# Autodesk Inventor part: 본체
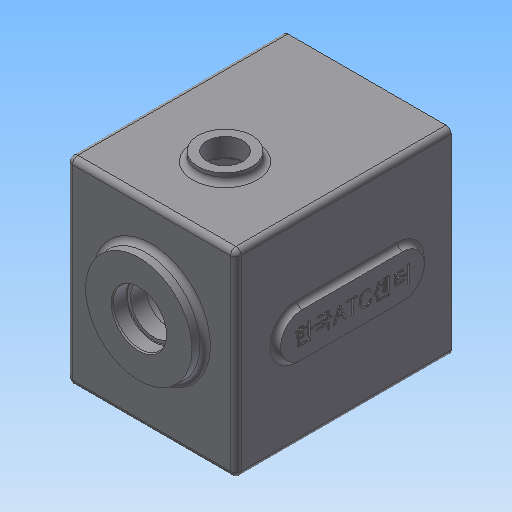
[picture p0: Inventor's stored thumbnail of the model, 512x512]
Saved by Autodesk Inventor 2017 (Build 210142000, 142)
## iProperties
Created: 2016-02
Part Number: 본체
Material: 알루미늄 6061
Document SubType Name: Modeling
Designer: mduedu
Density: 2.7 g/cm^3
Appearance: 기본값
Mass: 1511.55 g
Surface Area: 1073.15 cm^2
Volume: 559.832 cm^3
Author: mduedu
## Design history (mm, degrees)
sketch "스케치1"
  geometry: L1 (-47, -47)-(47, -47); L2 (47, -47)-(47, 63); L3 (47, 63)-(-47, 63); L4 (-47, 63)-(-47, -47); 2 further points
  constraints: 8 end point, 2 parallel, 1 horizontal, 1 midpoint, 1 perpendicular, 1 vertical alignment
  dimensions: "d0" = 94 distance of L2.end L3.end; "d155" = 110 distance of L1.end L2.end; "d156" = 47 distance from line of L1 point (0, 0)
extrude "돌출1" new body sketch "스케치1" distance "d2" = 120; taper "d3" = 0 deg
sketch "스케치3"
  geometry: L1 (47, -47)-(-47, -47) reference; L2 (47, 63)-(47, -47) reference; L3 (-47, 63)-(47, 63) reference; L4 (-47, -47)-(-47, 63) reference; L5 (37, 53)-(37, -37); L6 (37, -37)-(-37, -37); L7 (-37, -37)-(-37, 53); L8 (-37, 53)-(37, 53); 1 further point
  constraints: 8 end point, 3 other
  dimensions: "d226" = 10 distance between parallel lines of L8 L3
extrude "돌출3" cut sketch "스케치3" distance "d11" = 110; taper "d12" = 0 deg
sketch "스케치4"
  geometry: C1 r 21 at (0, 11); 1 further point
  constraints: 1 centre point, 1 vertical alignment
  dimensions: "d13" = 21 radius of C1; "d227" = 11 distance of point (0, 0) C1.centre
extrude "돌출4" join sketch "스케치4" distance "d16" = 7; taper "d17" = 0 deg
sketch "스케치5"
  geometry: C1 r 15 at (0, -20); 1 further point
  constraints: 1 centre point, 1 vertical alignment
  dimensions: "d18" = 15 radius of C1; "d20" = 20 distance of point (0, 0) C1.centre
extrude "돌출5" join sketch "스케치5" distance "d21" = 7; taper "d22" = 0 deg
sketch "스케치6"
  geometry: C1 r 30 at (0, 11); A1 r 21 centre (0, 11) between (8.978, -7.984) and (-8.978, -7.984) reference; 1 further point
  constraints: 1 centre point, 1 coincident
  dimensions: "d228" = 60 diameter of C1
extrude "돌출6" join sketch "스케치6" distance "d25" = 7; taper "d26" = -3 deg
hole "구멍1" diameter "d29" = 30; stored, may be unused: countersink angle "d33" = 90 deg, drill point angle "d35" = 0 deg; dims "d30" = 6, "d31" = 4, "d32" = 2, "d34" = 7, "d269" = 10, "d270" = 10
hole "구멍2" diameter "d38" = 22; stored, may be unused: countersink angle "d42" = 90 deg, drill point angle "d44" = 0 deg; dims "d36" = 10, "d37" = 10, "d39" = 6, "d40" = 4, "d41" = 2, "d43" = 7
hole "구멍3" diameter "d47" = 19; stored, may be unused: countersink angle "d51" = 90 deg, drill point angle "d53" = 0 deg; dims "d45" = 10, "d46" = 10, "d48" = 6, "d49" = 4, "d50" = 2, "d52" = 1
hole "구멍4" diameter "d56" = 30; stored, may be unused: countersink angle "d60" = 90 deg, drill point angle "d62" = 0 deg; dims "d57" = 6, "d58" = 4, "d59" = 2, "d61" = 8.3, "d271" = 10, "d272" = 10
hole "구멍5" diameter "d65" = 26; stored, may be unused: countersink angle "d69" = 90 deg, drill point angle "d71" = 0 deg; dims "d66" = 6, "d67" = 4, "d68" = 2, "d70" = 8, "d267" = 10, "d268" = 10
fillet "모깎기2" dims "d73" = 0.3
fillet "모깎기3" dims "d74" = 2
chamfer "모따기1" distance "d75" = 1; stored, may be unused: second distance "d76" = 2, angle "d77" = 45 deg
fillet "모깎기4" dims "d78" = 3
fillet "모깎기23" dims "d240" = 1
fillet "모깎기20" dims "d229" = 3
sketch "스케치23"
  geometry: L1 (-37, 53)-(37, 53) reference; L2 (37, 53)-(37, -37) reference; L3 (37, -37)-(-37, -37) reference; L4 (-37, -37)-(-37, 53) reference; L5 (44, -47)-(-44, -47) reference; L6 (47, 60)-(47, -44) reference; L7 (-44, 63)-(44, 63) reference; L8 (-47, -44)-(-47, 60) reference; C1 r 10 at (-37, 53); C2 r 10 at (37, 53); C3 r 10 at (-37, -37); C4 r 10 at (37, -37); A1 r 3 centre (-44, -44) between (-47, -44) and (-44, -47) reference; A2 r 3 centre (44, -44) between (44, -47) and (47, -44) reference; A3 r 3 centre (44, 60) between (47, 60) and (44, 63) reference; A4 r 3 centre (-44, 60) between (-44, 63) and (-47, 60) reference; 1 further point
  constraints: 4 centre point, 4 coincident, 3 equal radius
  dimensions: "d230" = 20 diameter of C1
extrude "돌출22" join sketch "스케치23" stored distance "d235" = 10; taper "d236" = 0 deg
fillet "모깎기21" dims "d237" = 3
node "작업 평면1"
fillet "모깎기22" dims "d239" = 1
sketch "스케치12"
  geometry: A1 r 10 centre (-37, 53) between (-34.692, 43.27) and (-27.27, 50.692) reference; A2 r 10 centre (37, 53) between (27.27, 50.692) and (34.692, 43.27) reference; A3 r 10 centre (37, -37) between (34.692, -27.27) and (27.27, -34.692) reference; A4 r 10 centre (-37, -37) between (-27.27, -34.692) and (-34.692, -27.27) reference; 5 further points
  constraints: 4 coincident
hole "구멍6" sketch "스케치12" at (-37, 53), (37, 53), (37, -37), (-37, -37) diameter "d122" = 3.242; stored, may be unused: countersink angle "d126" = 90 deg, drill point angle "d128" = 120 deg; dims "d123" = 7, "d124" = 4, "d125" = 2, "d127" = 9
sketch "스케치20"
  geometry: L1 (44, 0)-(-44, 0) reference; L2 (44, -120)-(-44, -120) reference; L3 (0, 0)-(0, -120); L4 (-44, -120)-(-44, 0) reference; L5 (44, 0)-(44, -120) reference; C1 r 10 at (0, -79)
  constraints: 2 end point, 1 centre point, 1 midpoint, 1 point on line
  dimensions: "d189" = 20 diameter of C1; "d190" = 41 distance from line of C1.centre L2
extrude "돌출19" cut sketch "스케치20" stored distance "d191" = 10; taper "d192" = 0 deg
sketch "스케치18"
  geometry: C1 r 15 at (0, -79); C2 r 10 at (0, -79) reference; 1 further point
  constraints: 1 centre point, 1 concentric
  dimensions: "d174" = 30 diameter of C1
extrude "돌출17" join sketch "스케치18" distance "d175" = 5; taper "d176" = 0 deg
fillet "모깎기16" dims "d177" = 3
sketch "스케치19"
  geometry: C1 r 15 at (24.351, 79); C2 r 10 at (24.351, 79) reference; 1 further point
  constraints: 1 centre point, 1 concentric
  dimensions: "d178" = 30 diameter of C1
extrude "돌출18" cut sketch "스케치19" distance "d181" = 5; taper "d182" = 0 deg
chamfer "모따기5" distance "d183" = 1; stored, may be unused: second distance "d184" = 2, angle "d185" = 45 deg
fillet "모깎기24" dims "d242" = 3, "d243" = 3
sketch "스케치24"
  geometry: L1 (-86, 64)-(-30, 64); L2 (-30, 64)-(-30, 40); L3 (-30, 40)-(-86, 40); L4 (-86, 40)-(-86, 64); L5 (0, 0)-(0, 104) reference; L6 (-86, 52)-(-30, 52); L7 (-58, 64)-(-58, 40); A1 r 12 centre (-86, 52) between (-86, 40) and (-86, 64); A2 r 12 centre (-30, 52) between (-30, 64) and (-30, 40); A3 r 12 centre (-30, 52) between (-30, 40) and (-30, 64); A4 r 12 centre (-86, 52) between (-86, 64) and (-86, 40); 2 further points
  constraints: 12 end point, 8 point on circle, 5 midpoint, 4 centre point, 2 parallel, 2 perpendicular, 1 horizontal, 1 horizontal alignment
  dimensions: "d244" = 58 distance between parallel lines of L7 L5; "d245" = 80 dimension on A2 A1; "d246" = 24 distance between parallel lines of L3 L1
extrude "돌출23" join sketch "스케치24" distance "d247" = 3; taper "d248" = 0 deg
fillet "모깎기25" dims "d249" = 3
sketch "스케치25"
  geometry: L1 (-30, 64)-(-86, 64) reference; L2 (-86, 40)-(-30, 40) reference; A1 r 12 centre (-86, 52) between (-86, 64) and (-86, 40) reference; A2 r 12 centre (-30, 52) between (-30, 40) and (-30, 64) reference; 3 further points
  constraints: 1 horizontal alignment, 1 midpoint, 1 vertical alignment, 1 other
feature "엠보싱3" sketch "스케치25" dims "d32" = 2, "d250" = 0.5, "d251" = 0
sketch "스케치26"
  geometry: L1 (14.367, 127)-(73.633, 127) reference; L2 (0, 0)-(88, 0) reference; L3 (88, 120)-(0, 120) reference; 5 further points
  constraints: 3 vertical alignment, 2 midpoint
  dimensions: "d252" = 35 distance from line of point (44, 35) L2; "d253" = 35 distance from line of point (44, 85) L3; "d254" = 50 distance of point (44, 35) point (44, 85) (derived)
hole "구멍8" sketch "스케치26" at (44, 85), (44, 35) diameter "d255" = 6.647; stored, may be unused: countersink angle "d259" = 90 deg, drill point angle "d261" = 118 deg; dims "d256" = 6, "d257" = 4, "d258" = 2, "d260" = 8
chamfer "모따기7" distance "d262" = 0.8; stored, may be unused: second distance "d263" = 2, angle "d264" = 30 deg
node "솔리드1"
node "투영된 루프1"
node "투영된 루프4"
node "투영된 루프5"
node "투영된 루프6"
